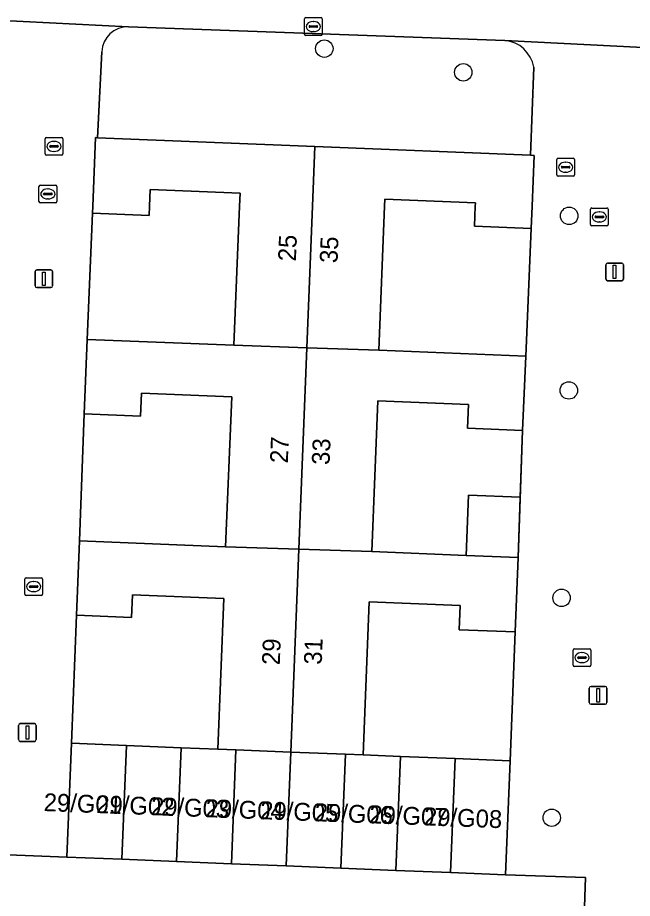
# Model space of a CAD drawing. Extents: x 160786 to 161429, y 386828 to 387485.
# Drawn here: x 161067.25 to 161101.74, y 387211.19 to 387260.56 of the extents above; entities that cross this region are included whole.
import ezdxf

# ---------------------------------------------------------------- set-up
doc = ezdxf.new("R2010")
doc.units = 0
for name, color, linetype in [('IMGEO_Boom', 7, 'Continuous'), ('IMGEO_Erf', 7, 'Continuous'), ('IMGEO_Groenvoorziening', 7, 'Continuous'), ('IMGEO_Kolk', 7, 'Continuous'), ('IMGEO_Lichtmast', 7, 'Continuous'), ('IMGEO_Muur', 7, 'Continuous'), ('IMGEO_Pand', 7, 'Continuous'), ('IMGEO_Pand_nummerreeks', 7, 'Continuous'), ('IMGEO_Rijbaan_lokaal_open', 7, 'Continuous'), ('IMGEO_Rioolput', 7, 'Continuous'), ('IMGEO_Voetpad_open', 7, 'Continuous')]:
    doc.layers.add(name, color=color, linetype=linetype)

msp = doc.modelspace()

# ---------------------------------------------------------------- linework, layer by layer
at = {"layer": 'IMGEO_Boom'}
for centre in [(161084.458, 387258.827), (161092.254, 387257.499), (161098.196, 387249.453), (161098.174, 387239.665), (161097.767, 387228.037), (161097.217, 387215.712)]:
    msp.add_circle(centre, 0.489, dxfattribs=at)
at = {"layer": 'IMGEO_Erf'}
for points in [[(161071.15, 387242.529), (161079.383, 387242.194), (161079.701, 387250), (161079.73, 387250.715), (161074.686, 387250.92), (161074.648, 387250), (161074.627, 387249.48), (161071.455, 387249.609)], [(161096.065, 387248.737), (161092.878, 387248.867), (161092.924, 387250), (161092.932, 387250.187), (161087.856, 387250.393), (161087.84, 387250), (161087.512, 387241.93), (161095.755, 387241.593)], [(161070.728, 387231.241), (161078.924, 387230.907), (161079.266, 387239.315), (161074.207, 387239.521), (161074.154, 387238.221), (161070.98, 387238.35)], [(161095.585, 387237.429), (161092.499, 387237.555), (161092.552, 387238.878), (161087.461, 387239.085), (161087.117, 387230.63), (161092.409, 387230.414), (161092.547, 387233.792), (161095.453, 387233.674)], [(161070.279, 387219.888), (161073.354, 387219.763), (161076.429, 387219.638), (161078.487, 387219.554), (161078.83, 387227.996), (161073.695, 387228.204), (161073.643, 387226.934), (161070.558, 387227.06)], [(161095.165, 387226.125), (161092.017, 387226.253), (161092.072, 387227.603), (161086.983, 387227.81), (161086.634, 387219.237), (161088.727, 387219.152), (161091.802, 387219.027), (161094.876, 387218.902)]]:
    msp.add_lwpolyline(points, close=True, dxfattribs=at)
at = {"layer": 'IMGEO_Groenvoorziening'}
for points in [[(161094.581, 387259.286), (161073.473, 387260.044)], [(161071.976, 387258.648), (161071.734, 387253.832), (161083.928, 387253.336), (161096.017, 387252.845), (161096.207, 387257.787)]]:
    msp.add_lwpolyline(points, dxfattribs=at)
for centre, radius, start, end in [((161073.425, 387258.595), 1.45, 88.0881, 177.913), ((161094.416, 387257.476), 1.818, 9.8629, 84.7916)]:
    msp.add_arc(centre, radius, start, end, dxfattribs=at)
at = {"layer": 'IMGEO_Kolk'}
for p, q in [((161083.343, 387259.638), (161083.343, 387260.49)), ((161083.418, 387260.564), (161084.27, 387260.564)), ((161084.344, 387260.49), (161084.344, 387259.638)), ((161083.602, 387260.058), (161083.602, 387260.07)), ((161084.04, 387260.021), (161083.642, 387260.021)), ((161083.645, 387260.107), (161084.043, 387260.107)), ((161083.831, 387260.344), (161083.856, 387260.344)), ((161084.086, 387260.07), (161084.086, 387260.058)), ((161084.27, 387259.564), (161083.418, 387259.564)), ((161083.854, 387259.784), (161083.829, 387259.784)), ((161068.453, 387250.252), (161068.453, 387251.104)), ((161068.528, 387251.178), (161069.38, 387251.178)), ((161069.454, 387251.104), (161069.454, 387250.252)), ((161068.712, 387250.672), (161068.712, 387250.684)), ((161069.15, 387250.635), (161068.752, 387250.635)), ((161068.755, 387250.721), (161069.153, 387250.721)), ((161068.941, 387250.958), (161068.966, 387250.958)), ((161069.196, 387250.684), (161069.196, 387250.672)), ((161069.38, 387250.178), (161068.528, 387250.178)), ((161068.964, 387250.398), (161068.939, 387250.398)), ((161099.387, 387248.966), (161099.387, 387249.818)), ((161099.462, 387249.892), (161100.314, 387249.892)), ((161099.875, 387249.672), (161099.9, 387249.672)), ((161100.388, 387249.818), (161100.388, 387248.966)), ((161099.646, 387249.386), (161099.646, 387249.398)), ((161100.084, 387249.349), (161099.686, 387249.349)), ((161099.689, 387249.435), (161100.087, 387249.435)), ((161099.898, 387249.112), (161099.873, 387249.112)), ((161100.13, 387249.398), (161100.13, 387249.386)), ((161100.314, 387248.892), (161099.462, 387248.892)), ((161067.655, 387228.242), (161067.655, 387229.094)), ((161067.73, 387229.168), (161068.582, 387229.168)), ((161068.143, 387228.948), (161068.168, 387228.948)), ((161068.656, 387229.094), (161068.656, 387228.242)), ((161067.914, 387228.662), (161067.914, 387228.674)), ((161068.352, 387228.625), (161067.954, 387228.625)), ((161067.957, 387228.711), (161068.355, 387228.711)), ((161068.166, 387228.388), (161068.141, 387228.388)), ((161068.398, 387228.674), (161068.398, 387228.662)), ((161068.582, 387228.168), (161067.73, 387228.168)), ((161098.414, 387224.261), (161098.414, 387225.113)), ((161098.489, 387225.187), (161099.341, 387225.187)), ((161098.902, 387224.967), (161098.927, 387224.967)), ((161099.415, 387225.113), (161099.415, 387224.261)), ((161098.673, 387224.681), (161098.673, 387224.693)), ((161099.111, 387224.644), (161098.713, 387224.644)), ((161098.716, 387224.73), (161099.114, 387224.73)), ((161098.925, 387224.407), (161098.9, 387224.407)), ((161099.157, 387224.693), (161099.157, 387224.681)), ((161099.341, 387224.187), (161098.489, 387224.187))]:
    msp.add_line(p, q, dxfattribs=at)
for points in [[(161083.343, 387259.638), (161083.343, 387260.49)], [(161083.418, 387260.564), (161084.27, 387260.564)], [(161084.344, 387260.49), (161084.344, 387259.638)], [(161084.27, 387259.564), (161083.418, 387259.564)], [(161068.453, 387250.252), (161068.453, 387251.104)], [(161068.528, 387251.178), (161069.38, 387251.178)], [(161069.454, 387251.104), (161069.454, 387250.252)], [(161069.38, 387250.178), (161068.528, 387250.178)], [(161099.387, 387248.966), (161099.387, 387249.818)], [(161099.462, 387249.892), (161100.314, 387249.892)], [(161100.388, 387249.818), (161100.388, 387248.966)], [(161100.314, 387248.892), (161099.462, 387248.892)], [(161067.655, 387228.242), (161067.655, 387229.094)], [(161067.73, 387229.168), (161068.582, 387229.168)], [(161068.656, 387229.094), (161068.656, 387228.242)], [(161068.582, 387228.168), (161067.73, 387228.168)], [(161098.414, 387224.261), (161098.414, 387225.113)], [(161098.489, 387225.187), (161099.341, 387225.187)], [(161099.415, 387225.113), (161099.415, 387224.261)], [(161099.341, 387224.187), (161098.489, 387224.187)]]:
    msp.add_lwpolyline(points, dxfattribs=at)
for centre, radius, start, end in [((161083.42, 387260.488), 0.0765, 91.552, 178.448), ((161083.42, 387260.488), 0.0765, 91.552, 178.448), ((161084.268, 387260.488), 0.0765, 1.552, 88.448), ((161084.268, 387260.488), 0.0765, 1.552, 88.448), ((161083.642, 387260.067), 0.0403, 85.8775, 175.7526), ((161083.639, 387260.057), 0.0366, 178.938, 274.7102), ((161084.043, 387260.064), 0.043, 264.8664, 352.4533), ((161084.047, 387260.069), 0.0386, 1.7309, 96.639), ((161083.42, 387259.64), 0.0765, 181.552, 268.448), ((161083.42, 387259.64), 0.0765, 181.552, 268.448), ((161084.268, 387259.64), 0.0765, 271.552, 358.448), ((161084.268, 387259.64), 0.0765, 271.552, 358.448), ((161068.53, 387251.102), 0.0765, 91.552, 178.448), ((161068.53, 387251.102), 0.0765, 91.552, 178.448), ((161069.378, 387251.102), 0.0765, 1.552, 88.448), ((161069.378, 387251.102), 0.0765, 1.552, 88.448), ((161068.752, 387250.681), 0.0403, 85.8775, 175.7526), ((161068.749, 387250.671), 0.0366, 178.938, 274.7102), ((161069.153, 387250.678), 0.043, 264.8664, 352.4533), ((161069.157, 387250.683), 0.0386, 1.7309, 96.639), ((161068.53, 387250.254), 0.0765, 181.552, 268.448), ((161068.53, 387250.254), 0.0765, 181.552, 268.448), ((161069.378, 387250.254), 0.0765, 271.552, 358.448), ((161069.378, 387250.254), 0.0765, 271.552, 358.448), ((161099.464, 387249.816), 0.0765, 91.552, 178.448), ((161099.464, 387249.816), 0.0765, 91.552, 178.448), ((161100.312, 387249.816), 0.0765, 1.552, 88.448), ((161100.312, 387249.816), 0.0765, 1.552, 88.448), ((161099.686, 387249.395), 0.0403, 85.8775, 175.7526), ((161099.683, 387249.385), 0.0366, 178.938, 274.7102), ((161100.087, 387249.392), 0.043, 264.8664, 352.4533), ((161100.091, 387249.397), 0.0386, 1.7309, 96.639), ((161099.464, 387248.968), 0.0765, 181.552, 268.448), ((161099.464, 387248.968), 0.0765, 181.552, 268.448), ((161100.312, 387248.968), 0.0765, 271.552, 358.448), ((161100.312, 387248.968), 0.0765, 271.552, 358.448), ((161067.732, 387229.092), 0.0765, 91.552, 178.448), ((161067.732, 387229.092), 0.0765, 91.552, 178.448), ((161068.58, 387229.092), 0.0765, 1.552, 88.448), ((161068.58, 387229.092), 0.0765, 1.552, 88.448), ((161067.954, 387228.671), 0.0403, 85.8775, 175.7526), ((161067.951, 387228.661), 0.0366, 178.938, 274.7102), ((161068.355, 387228.668), 0.043, 264.8664, 352.4533), ((161068.359, 387228.673), 0.0386, 1.7309, 96.639), ((161067.732, 387228.244), 0.0765, 181.552, 268.448), ((161067.732, 387228.244), 0.0765, 181.552, 268.448), ((161068.58, 387228.244), 0.0765, 271.552, 358.448), ((161068.58, 387228.244), 0.0765, 271.552, 358.448), ((161098.491, 387225.111), 0.0765, 91.552, 178.448), ((161098.491, 387225.111), 0.0765, 91.552, 178.448), ((161099.339, 387225.111), 0.0765, 1.552, 88.448), ((161099.339, 387225.111), 0.0765, 1.552, 88.448), ((161098.713, 387224.69), 0.0403, 85.8775, 175.7526), ((161098.71, 387224.68), 0.0366, 178.938, 274.7102), ((161099.114, 387224.687), 0.043, 264.8664, 352.4533), ((161099.118, 387224.692), 0.0386, 1.7309, 96.639), ((161098.491, 387224.263), 0.0765, 181.552, 268.448), ((161098.491, 387224.263), 0.0765, 181.552, 268.448), ((161099.339, 387224.263), 0.0765, 271.552, 358.448), ((161099.339, 387224.263), 0.0765, 271.552, 358.448)]:
    msp.add_arc(centre, radius, start, end, dxfattribs=at)
for centre, major_axis, ratio, start_param, end_param in [((161083.83, 387260.064), (-0.387, 0.002), 0.722429, 4.712389, 7.853982), ((161083.855, 387260.064), (-0.39, 0.002), 0.717154, 1.570796, 4.712389), ((161068.94, 387250.678), (-0.387, 0.002), 0.722429, 4.712389, 7.853982), ((161068.965, 387250.678), (-0.39, 0.002), 0.717154, 1.570796, 4.712389), ((161099.874, 387249.392), (-0.387, 0.002), 0.722429, 4.712389, 7.853982), ((161099.899, 387249.392), (-0.39, 0.002), 0.717154, 1.570796, 4.712389), ((161068.142, 387228.668), (-0.387, 0.002), 0.722429, 4.712389, 7.853982), ((161068.167, 387228.668), (-0.39, 0.002), 0.717154, 1.570796, 4.712389), ((161098.901, 387224.687), (-0.387, 0.002), 0.722429, 4.712389, 7.853982), ((161098.926, 387224.687), (-0.39, 0.002), 0.717154, 1.570796, 4.712389)]:
    msp.add_ellipse(centre, major_axis=major_axis, ratio=ratio, start_param=start_param, end_param=end_param, dxfattribs=at)
at = {"layer": 'IMGEO_Lichtmast'}
for p, q in [((161100.25, 387245.909), (161100.25, 387246.709)), ((161100.25, 387246.709), (161100.25, 387245.909)), ((161100.35, 387246.809), (161101.14, 387246.809)), ((161101.14, 387246.809), (161100.35, 387246.809)), ((161101.24, 387246.709), (161101.24, 387245.909)), ((161101.24, 387245.909), (161101.24, 387246.709)), ((161068.23, 387245.527), (161068.23, 387246.327)), ((161068.23, 387246.327), (161068.23, 387245.527)), ((161068.33, 387246.427), (161069.12, 387246.427)), ((161069.12, 387246.427), (161068.33, 387246.427)), ((161069.22, 387246.327), (161069.22, 387245.527)), ((161069.22, 387245.527), (161069.22, 387246.327)), ((161101.14, 387245.809), (161100.35, 387245.809)), ((161100.35, 387245.809), (161101.14, 387245.809)), ((161069.12, 387245.427), (161068.33, 387245.427)), ((161068.33, 387245.427), (161069.12, 387245.427)), ((161099.319, 387222.173), (161099.319, 387222.973)), ((161099.319, 387222.973), (161099.319, 387222.173)), ((161099.419, 387223.073), (161100.209, 387223.073)), ((161100.209, 387223.073), (161099.419, 387223.073)), ((161100.309, 387222.973), (161100.309, 387222.173)), ((161100.309, 387222.173), (161100.309, 387222.973)), ((161100.209, 387222.073), (161099.419, 387222.073)), ((161099.419, 387222.073), (161100.209, 387222.073)), ((161067.406, 387220.99), (161068.196, 387220.99)), ((161068.196, 387220.99), (161067.406, 387220.99)), ((161067.306, 387220.09), (161067.306, 387220.89)), ((161067.306, 387220.89), (161067.306, 387220.09)), ((161068.296, 387220.89), (161068.296, 387220.09)), ((161068.296, 387220.09), (161068.296, 387220.89)), ((161068.196, 387219.99), (161067.406, 387219.99)), ((161067.406, 387219.99), (161068.196, 387219.99))]:
    msp.add_line(p, q, dxfattribs=at)
for points in [[(161100.67, 387246.684), (161100.82, 387246.684), (161100.82, 387245.934), (161100.67, 387245.934), (161100.67, 387246.684)], [(161068.65, 387246.302), (161068.8, 387246.302), (161068.8, 387245.552), (161068.65, 387245.552), (161068.65, 387246.302)], [(161099.739, 387222.948), (161099.889, 387222.948), (161099.889, 387222.198), (161099.739, 387222.198), (161099.739, 387222.948)], [(161067.726, 387220.865), (161067.876, 387220.865), (161067.876, 387220.115), (161067.726, 387220.115), (161067.726, 387220.865)]]:
    msp.add_lwpolyline(points, dxfattribs=at)
for centre, start, end in [((161100.35, 387246.709), 90, 180), ((161100.35, 387246.709), 90, 180), ((161101.14, 387246.709), 0, 90), ((161101.14, 387246.709), 360, 90), ((161068.33, 387246.327), 90, 180), ((161068.33, 387246.327), 90, 180), ((161069.12, 387246.327), 0, 90), ((161069.12, 387246.327), 360, 90), ((161100.35, 387245.909), 180, 270), ((161100.35, 387245.909), 180, 270), ((161101.14, 387245.909), 270, 0), ((161101.14, 387245.909), 270, 0), ((161068.33, 387245.527), 180, 270), ((161068.33, 387245.527), 180, 270), ((161069.12, 387245.527), 270, 0), ((161069.12, 387245.527), 270, 0), ((161099.419, 387222.973), 90, 180), ((161099.419, 387222.973), 90, 180), ((161100.209, 387222.973), 0, 90), ((161100.209, 387222.973), 360, 90), ((161099.419, 387222.173), 180, 270), ((161099.419, 387222.173), 180, 270), ((161100.209, 387222.173), 270, 0), ((161100.209, 387222.173), 270, 0), ((161067.406, 387220.89), 90, 180), ((161067.406, 387220.89), 90, 180), ((161068.196, 387220.89), 0, 90), ((161068.196, 387220.89), 360, 90), ((161067.406, 387220.09), 180, 270), ((161067.406, 387220.09), 180, 270), ((161068.196, 387220.09), 270, 0), ((161068.196, 387220.09), 270, 0)]:
    msp.add_arc(centre, 0.1, start, end, dxfattribs=at)
at = {"layer": 'IMGEO_Muur'}
for points in [[(161071.455, 387249.609), (161071.15, 387242.529)], [(161095.755, 387241.593), (161096.065, 387248.737)], [(161070.728, 387231.241), (161070.98, 387238.35)], [(161095.585, 387237.429), (161095.334, 387230.294)], [(161070.279, 387219.888), (161070.558, 387227.06)], [(161095.165, 387226.125), (161094.876, 387218.902)]]:
    msp.add_lwpolyline(points, dxfattribs=at)
at = {"layer": 'IMGEO_Pand'}
for points in [[(161071.734, 387253.832), (161071.627, 387253.836), (161071.471, 387250), (161071.455, 387249.609), (161074.627, 387249.48), (161074.648, 387250), (161074.686, 387250.92), (161079.73, 387250.715), (161079.701, 387250), (161079.383, 387242.194), (161083.478, 387242.062), (161083.795, 387250), (161083.928, 387253.336)], [(161087.84, 387250), (161087.856, 387250.393), (161092.932, 387250.187), (161092.924, 387250), (161092.878, 387248.867), (161096.065, 387248.737), (161096.116, 387250), (161096.232, 387252.836), (161096.017, 387252.845), (161083.928, 387253.336), (161083.795, 387250), (161083.478, 387242.062), (161087.512, 387241.93)], [(161070.98, 387238.35), (161074.154, 387238.221), (161074.207, 387239.521), (161079.266, 387239.315), (161078.924, 387230.907), (161083.027, 387230.767), (161083.478, 387242.062), (161079.383, 387242.194), (161071.15, 387242.529)], [(161095.755, 387241.593), (161087.512, 387241.93), (161083.478, 387242.062), (161083.027, 387230.767), (161087.117, 387230.63), (161087.461, 387239.085), (161092.552, 387238.878), (161092.499, 387237.555), (161095.585, 387237.429)], [(161095.453, 387233.674), (161092.547, 387233.792), (161092.409, 387230.414), (161095.334, 387230.294)], [(161070.558, 387227.06), (161073.643, 387226.934), (161073.695, 387228.204), (161078.83, 387227.996), (161078.487, 387219.554), (161079.503, 387219.514), (161082.573, 387219.395), (161083.027, 387230.767), (161078.924, 387230.907), (161070.728, 387231.241)], [(161095.334, 387230.294), (161092.409, 387230.414), (161087.117, 387230.63), (161083.027, 387230.767), (161082.573, 387219.395), (161085.653, 387219.275), (161086.634, 387219.237), (161086.983, 387227.81), (161092.072, 387227.603), (161092.017, 387226.253), (161095.165, 387226.125)], [(161070.279, 387219.888), (161070.02, 387213.51), (161073.094, 387213.385), (161073.354, 387219.763)], [(161073.354, 387219.763), (161073.094, 387213.385), (161076.169, 387213.26), (161076.429, 387219.638)], [(161076.429, 387219.638), (161076.169, 387213.26), (161079.244, 387213.135), (161079.503, 387219.514), (161078.487, 387219.554)], [(161082.573, 387219.395), (161079.503, 387219.514), (161079.244, 387213.135), (161082.318, 387213.01)], [(161082.318, 387213.01), (161085.393, 387212.884), (161085.653, 387219.275), (161082.573, 387219.395)], [(161086.634, 387219.237), (161085.653, 387219.275), (161085.393, 387212.884), (161088.467, 387212.759), (161088.727, 387219.152)], [(161088.727, 387219.152), (161088.467, 387212.759), (161091.542, 387212.634), (161091.802, 387219.027)], [(161091.802, 387219.027), (161091.542, 387212.634), (161094.616, 387212.509), (161094.876, 387218.902)]]:
    msp.add_lwpolyline(points, close=True, dxfattribs=at)
at = {"layer": 'IMGEO_Rijbaan_lokaal_open'}
for points in [[(161099.107, 387212.357), (161094.616, 387212.509), (161091.542, 387212.634), (161088.467, 387212.759), (161085.393, 387212.884), (161082.318, 387213.01), (161079.244, 387213.135), (161076.169, 387213.26), (161073.094, 387213.385), (161070.02, 387213.51), (161064.832, 387213.699), (161061.778, 387213.825), (161058.724, 387213.952), (161055.67, 387214.078), (161052.616, 387214.204), (161049.562, 387214.331), (161046.508, 387214.457), (161043.454, 387214.584), (161040.4, 387214.71), (161039.534, 387199.642)], [(161032.801, 387190.374), (161098.276, 387187.786), (161099.107, 387212.357)]]:
    msp.add_lwpolyline(points, dxfattribs=at)
at = {"layer": 'IMGEO_Rioolput'}
for p, q in [((161068.795, 387252.921), (161068.795, 387253.773)), ((161068.87, 387253.847), (161069.722, 387253.847)), ((161069.283, 387253.627), (161069.308, 387253.627)), ((161069.796, 387253.773), (161069.796, 387252.921)), ((161069.054, 387253.341), (161069.054, 387253.353)), ((161069.492, 387253.304), (161069.094, 387253.304)), ((161069.097, 387253.39), (161069.495, 387253.39)), ((161069.306, 387253.067), (161069.281, 387253.067)), ((161069.538, 387253.353), (161069.538, 387253.341)), ((161069.722, 387252.847), (161068.87, 387252.847)), ((161097.495, 387251.752), (161097.495, 387252.604)), ((161097.57, 387252.678), (161098.422, 387252.678)), ((161098.496, 387252.604), (161098.496, 387251.752)), ((161097.754, 387252.172), (161097.754, 387252.184)), ((161098.192, 387252.135), (161097.794, 387252.135)), ((161097.797, 387252.221), (161098.195, 387252.221)), ((161097.983, 387252.458), (161098.008, 387252.458)), ((161098.238, 387252.184), (161098.238, 387252.172)), ((161098.422, 387251.678), (161097.57, 387251.678)), ((161098.006, 387251.898), (161097.981, 387251.898))]:
    msp.add_line(p, q, dxfattribs=at)
for points in [[(161068.795, 387252.921), (161068.795, 387253.773)], [(161068.87, 387253.847), (161069.722, 387253.847)], [(161069.796, 387253.773), (161069.796, 387252.921)], [(161069.722, 387252.847), (161068.87, 387252.847)], [(161097.495, 387251.752), (161097.495, 387252.604)], [(161097.57, 387252.678), (161098.422, 387252.678)], [(161098.496, 387252.604), (161098.496, 387251.752)], [(161098.422, 387251.678), (161097.57, 387251.678)]]:
    msp.add_lwpolyline(points, dxfattribs=at)
for centre, radius, start, end in [((161068.872, 387253.771), 0.0765, 91.552, 178.448), ((161068.872, 387253.771), 0.0765, 91.552, 178.448), ((161069.72, 387253.771), 0.0765, 1.552, 88.448), ((161069.72, 387253.771), 0.0765, 1.552, 88.448), ((161069.094, 387253.35), 0.0403, 85.8775, 175.7526), ((161069.091, 387253.34), 0.0366, 178.938, 274.7102), ((161069.495, 387253.347), 0.043, 264.8664, 352.4533), ((161069.499, 387253.352), 0.0386, 1.7309, 96.639), ((161068.872, 387252.923), 0.0765, 181.552, 268.448), ((161068.872, 387252.923), 0.0765, 181.552, 268.448), ((161069.72, 387252.923), 0.0765, 271.552, 358.448), ((161069.72, 387252.923), 0.0765, 271.552, 358.448), ((161097.572, 387252.602), 0.0765, 91.552, 178.448), ((161097.572, 387252.602), 0.0765, 91.552, 178.448), ((161098.42, 387252.602), 0.0765, 1.552, 88.448), ((161098.42, 387252.602), 0.0765, 1.552, 88.448), ((161097.794, 387252.181), 0.0403, 85.8775, 175.7526), ((161097.791, 387252.171), 0.0366, 178.938, 274.7102), ((161098.195, 387252.178), 0.043, 264.8664, 352.4533), ((161098.199, 387252.183), 0.0386, 1.7309, 96.639), ((161097.572, 387251.754), 0.0765, 181.552, 268.448), ((161097.572, 387251.754), 0.0765, 181.552, 268.448), ((161098.42, 387251.754), 0.0765, 271.552, 358.448), ((161098.42, 387251.754), 0.0765, 271.552, 358.448)]:
    msp.add_arc(centre, radius, start, end, dxfattribs=at)
for centre, major_axis, ratio, start_param, end_param in [((161069.282, 387253.347), (-0.387, 0.002), 0.722429, 4.712389, 7.853982), ((161069.307, 387253.347), (-0.39, 0.002), 0.717154, 1.570796, 4.712389), ((161097.982, 387252.178), (-0.387, 0.002), 0.722429, 4.712389, 7.853982), ((161098.007, 387252.178), (-0.39, 0.002), 0.717154, 1.570796, 4.712389)]:
    msp.add_ellipse(centre, major_axis=major_axis, ratio=ratio, start_param=start_param, end_param=end_param, dxfattribs=at)
at = {"layer": 'IMGEO_Voetpad_open'}
for points in [[(161073.473, 387260.044), (161066.075, 387260.424)], [(161066.075, 387260.424), (161073.473, 387260.044), (161094.581, 387259.286), (161105.29, 387258.743), (161129.989, 387257.842)], [(161066.745, 387259.265), (161066.475, 387253.962), (161066.311, 387250), (161066.304, 387249.823), (161066.026, 387242.671), (161065.854, 387238.51), (161065.701, 387234.089), (161065.609, 387231.425), (161065.434, 387227.189), (161065.093, 387219.999), (161064.832, 387213.699), (161070.02, 387213.51), (161070.279, 387219.888), (161070.558, 387227.06), (161070.728, 387231.241), (161070.98, 387238.35)], [(161105.29, 387258.743), (161094.581, 387259.286)], [(161070.98, 387238.35), (161071.15, 387242.529), (161071.455, 387249.609), (161071.471, 387250), (161071.627, 387253.836), (161071.734, 387253.832), (161071.976, 387258.648)], [(161096.207, 387257.787), (161096.017, 387252.845), (161096.232, 387252.836), (161096.116, 387250), (161096.065, 387248.737), (161095.755, 387241.593), (161095.585, 387237.429), (161095.453, 387233.674), (161095.334, 387230.294), (161095.165, 387226.125), (161094.876, 387218.902), (161094.616, 387212.509), (161099.107, 387212.357), (161098.276, 387187.786), (161098.215, 387185.98), (161098.029, 387183.585), (161097.659, 387174.419), (161097.233, 387163.345)]]:
    msp.add_lwpolyline(points, dxfattribs=at)
for centre, radius, start, end in [((161073.425, 387258.595), 1.45, 88.0881, 177.913), ((161094.416, 387257.476), 1.818, 9.8629, 84.7916)]:
    msp.add_arc(centre, radius, start, end, dxfattribs=at)

# ---------------------------------------------------------------- texts
at = {"layer": 'IMGEO_Pand_nummerreeks'}
for s, rotation, p in [('25', 87.7115, (161082.862, 387246.887)), ('35', 87.7485, (161085.197, 387246.79)), ('27', 87.7115, (161082.41, 387235.571)), ('33', 87.7473, (161084.752, 387235.478)), ('29', 87.7115, (161081.958, 387224.255)), ('31', 87.7485, (161084.311, 387224.28)), ('29/G01', 357.8573, (161068.704, 387216.088)), ('29/G02', 357.8573, (161071.65, 387215.978)), ('29/G03', 357.8573, (161074.719, 387215.863)), ('29/G04', 357.8573, (161077.781, 387215.748)), ('29/G05', 357.8573, (161080.844, 387215.634)), ('29/G06', 357.8573, (161083.906, 387215.519)), ('29/G07', 357.8573, (161086.969, 387215.405)), ('29/G08', 357.8573, (161090.034, 387215.29))]:
    msp.add_text(s, height=1, rotation=rotation, dxfattribs=at).set_placement(p)

doc.saveas('drawing.dxf')
